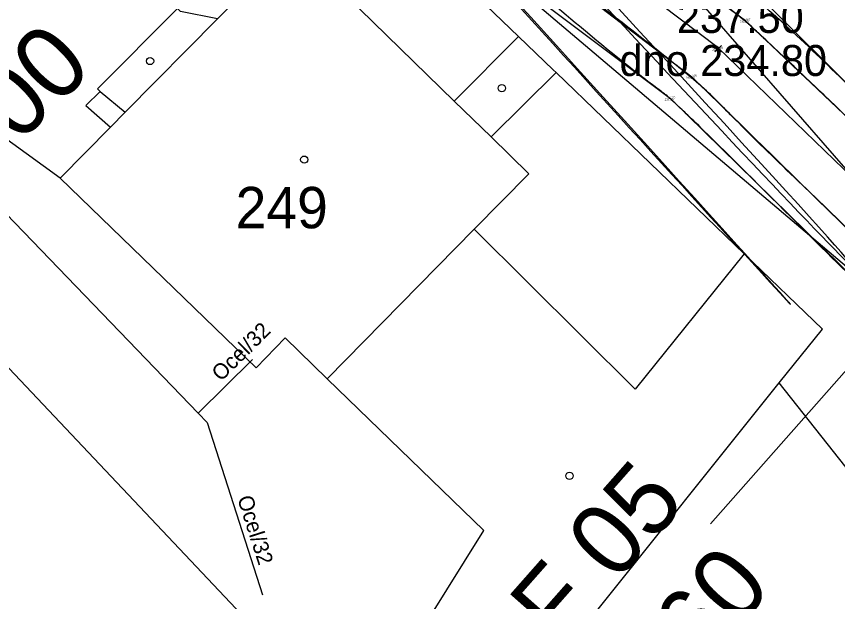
# Model space of a CAD drawing. Extents: x -555757 to -553364, y -1100723 to -1096439.
# Drawn here: x -554318.17 to -554278.45, y -1100564.79 to -1100536.48 of the extents above; entities that cross this region are included whole.
import ezdxf

# ---------------------------------------------------------------- set-up
doc = ezdxf.new("R2010")
doc.units = 0
for name, color, linetype in [('00_NÁVRH - 0.18 mm', 7, 'Continuous'), ('00_NÁVRH - 0.35 mm', 7, 'Continuous'), ('00_NÁVRH - Řezy', 7, 'Continuous'), ('01_HLADINA', 7, 'Continuous'), ('05_SÍTĚ - plynovod NTL', 7, 'Continuous'), ('05_SÍTĚ - vedení VN - nadzemní', 7, 'Continuous'), ('20', 7, 'Continuous'), ('BUDOVY', 7, 'Continuous'), ('C$SLO$PARCELY', 7, 'Continuous'), ('Geodet. výšky - netisknuté', 7, 'Continuous'), ('HRANA$SVAHU', 7, 'Continuous'), ('HRANICE$PARCELY', 7, 'Continuous'), ('OSA$KOLEJI', 7, 'Continuous'), ('POPIS', 7, 'Continuous'), ('ROZHRANI', 7, 'Continuous'), ('SLOUPY', 7, 'Continuous'), ('SLUCKOV$$C$RA', 7, 'Continuous'), ('VYSKA_PODR_BOD', 7, 'Continuous')]:
    doc.layers.add(name, color=color, linetype=linetype)

# ---------------------------------------------------------------- blocks, each defined once
blk = doc.blocks.new('POINT_DISPLAY')
blk.add_line((0, 0), (0, 0))
blk = doc.blocks.new('4$02')
at = {"layer": 'SLOUPY'}
blk.add_circle((0, 0), 0.175, dxfattribs=at)
blk = doc.blocks.new('BOD')
at = {"layer": 'POPIS'}
for p, q in [((-0.283, -0.283), (0.283, 0.283)), ((-0.283, 0.283), (0.283, -0.283))]:
    blk.add_line(p, q, dxfattribs=at)

msp = doc.modelspace()

# ---------------------------------------------------------------- linework, layer by layer
at = {"layer": '00_NÁVRH - 0.18 mm'}
msp.add_lwpolyline([(-554230.466, -1100601.206), (-554249.164, -1100583.038), (-554263.07, -1100566.98), (-554269.426, -1100554.136), (-554270.586, -1100551.573), (-554271.594, -1100550.189), (-554284.219, -1100538.005), (-554306.94, -1100520.848), (-554308.081, -1100519.365), (-554313.597, -1100512.423), (-554314.94, -1100505.715), (-554315.308, -1100495.76), (-554315.472, -1100482.811), (-554315.568, -1100470.17)], dxfattribs=at)
for points in [[(-554058.34, -1100594.24), (-554064.27, -1100591.415), (-554069.894, -1100588.736), (-554070.2, -1100588.59), (-554070.622, -1100588.302), (-554073.49, -1100586.347), (-554075.45, -1100585.01), (-554079.1, -1100582.531), (-554080.049, -1100581.874), (-554080.7, -1100581.481), (-554081.481, -1100581.304), (-554087.875, -1100580.272), (-554092.015, -1100579.605), (-554097.661, -1100578.708), (-554101.142, -1100578.133), (-554103.33, -1100577.967), (-554104.353, -1100578.095), (-554110.104, -1100579.897), (-554119.235, -1100582.7), (-554134.394, -1100587.389), (-554135.14, -1100587.62), (-554135.88, -1100587.767), (-554163.968, -1100593.356), (-554164.64, -1100593.5), (-554165.523, -1100593.676), (-554179.48, -1100596.685), (-554194.32, -1100599.87), (-554206.989, -1100602.104), (-554211.391, -1100602.887), (-554215.452, -1100603.598), (-554218.301, -1100604.127), (-554220.59, -1100604.491), (-554221.645, -1100604.411), (-554222.588, -1100604.119), (-554224.36, -1100602.886), (-554226.55, -1100601.265), (-554230.862, -1100598.151), (-554231.32, -1100597.82), (-554232.374, -1100596.759), (-554235.586, -1100593.426), (-554239.515, -1100589.37), (-554243.986, -1100584.748), (-554247.71, -1100580.92), (-554249.936, -1100577.477), (-554252.665, -1100573.15), (-554257.62, -1100565.38), (-554264.631, -1100555.299), (-554268.645, -1100549.529), (-554269.73, -1100547.97), (-554270.489, -1100547.211), (-554275.85, -1100541.875), (-554281.97, -1100535.78), (-554287.906, -1100531.237), (-554302.937, -1100521.677), (-554058.34, -1100594.24), (-554302.937, -1100521.677)], [(-554047.86, -1100606.09), (-554063.146, -1100601.815), (-554071.814, -1100599.393), (-554074.245, -1100598.71), (-554074.95, -1100598.43), (-554075.799, -1100598.044), (-554076.704, -1100597.516), (-554082.278, -1100594.33), (-554084.54, -1100593.047), (-554085.407, -1100592.634), (-554086.399, -1100592.326), (-554087.509, -1100592.104), (-554096.333, -1100590.269), (-554099.874, -1100589.549), (-554100.557, -1100589.404), (-554101.037, -1100589.369), (-554101.552, -1100589.414), (-554102.59, -1100589.645), (-554107.727, -1100590.768), (-554129.464, -1100595.608), (-554132.384, -1100596.23), (-554132.88, -1100596.318), (-554134.554, -1100596.539), (-554152.022, -1100598.865), (-554161.802, -1100600.155), (-554162.744, -1100600.318), (-554163.338, -1100600.456), (-554165.331, -1100601.02), (-554176.765, -1100604.247), (-554189.626, -1100607.8), (-554194.598, -1100609.179), (-554196.355, -1100609.599), (-554198.704, -1100609.736), (-554203.748, -1100609.834), (-554214.875, -1100610.027), (-554219.792, -1100610.102), (-554223.403, -1100610.173), (-554224.348, -1100610.104), (-554224.869, -1100609.756), (-554225.457, -1100609.217), (-554228.695, -1100606.291), (-554234.196, -1100601.385), (-554241.685, -1100594.776), (-554249.868, -1100587.59), (-554251.102, -1100586.477), (-554253.665, -1100583.954), (-554260.074, -1100577.697), (-554266.777, -1100571.14), (-554267.547, -1100570.379), (-554267.995, -1100569.734), (-554268.443, -1100568.902), (-554268.664, -1100568.278), (-554270.099, -1100564.014), (-554272.97, -1100555.371), (-554273.54, -1100553.674), (-554273.85, -1100553.041), (-554274.307, -1100552.435), (-554274.896, -1100551.869), (-554275.985, -1100550.799), (-554278.698, -1100548.209), (-554284.66, -1100542.226), (-554286.16, -1100540.826), (-554286.536, -1100540.462), (-554286.752, -1100540.28), (-554286.997, -1100540.101), (-554289.311, -1100538.365), (-554299.045, -1100530.122), (-554303.449, -1100525.797), (-554305.461, -1100524.163), (-554047.86, -1100606.09), (-554305.461, -1100524.163)]]:
    msp.add_open_spline(points, degree=3, dxfattribs=at)
at = {"layer": '00_NÁVRH - 0.35 mm'}
for points in [[(-554261.18, -1100566.187), (-554261.287, -1100566.026), (-554262.205, -1100564.307), (-554264.13, -1100560.566), (-554266.956, -1100555.04), (-554269.115, -1100550.897), (-554269.784, -1100549.561), (-554270.23, -1100548.864), (-554270.932, -1100548.082), (-554271.706, -1100547.35), (-554272.831, -1100546.276), (-554274.362, -1100544.823), (-554276.402, -1100542.876), (-554279.345, -1100540.052), (-554281.593, -1100537.929), (-554282.318, -1100537.246), (-554282.905, -1100536.713), (-554283.251, -1100536.425), (-554284.229, -1100535.698), (-554285.73, -1100534.585), (-554286.937, -1100533.66), (-554288.679, -1100532.362), (-554296.351, -1100526.833), (-554303.325, -1100522.059), (-554261.234, -1100566.107), (-554299.826, -1100524.428)], [(-554264.589, -1100568.17), (-554264.717, -1100567.968), (-554265.365, -1100566.881), (-554266.161, -1100565.265), (-554268.948, -1100559.629), (-554270.726, -1100555.972), (-554272.297, -1100552.9), (-554272.836, -1100551.874), (-554273.561, -1100551.08), (-554275.318, -1100549.374), (-554278.961, -1100545.794), (-554283.166, -1100541.692), (-554284.82, -1100540.047), (-554285.492, -1100539.455), (-554286.639, -1100538.528), (-554295.981, -1100531.243), (-554303.386, -1100525.154), (-554305.07, -1100523.778), (-554264.653, -1100568.069), (-554304.227, -1100524.466)]]:
    msp.add_open_spline(points, degree=3, dxfattribs=at)
at = {"layer": '00_NÁVRH - Řezy'}
msp.add_line((-554284.593, -1100561.029), (-554264.872, -1100538.673), dxfattribs=at)
at = {"layer": '01_HLADINA'}
for points in [[(-554303.325, -1100522.059), (-554300.992, -1100523.638), (-554296.049, -1100526.985), (-554290.632, -1100530.919), (-554287.105, -1100533.522), (-554285.641, -1100534.66), (-554284.408, -1100535.575), (-554283.446, -1100536.259), (-554282.815, -1100536.784), (-554282.268, -1100537.291), (-554281.086, -1100538.41), (-554279.101, -1100540.272), (-554276.707, -1100542.588), (-554274.536, -1100544.663), (-554272.962, -1100546.145), (-554271.829, -1100547.242), (-554270.928, -1100548.07), (-554270.249, -1100548.784), (-554269.657, -1100549.746), (-554268.678, -1100551.862), (-554266.678, -1100555.472), (-554264.463, -1100559.99), (-554262.518, -1100563.617), (-554261.613, -1100565.54), (-554261.216, -1100566.134), (-554261.18, -1100566.187)], [(-554265.965, -1100565.681), (-554266.03, -1100565.542), (-554266.988, -1100563.505), (-554268.662, -1100560.317), (-554270.589, -1100556.128), (-554272, -1100553.616), (-554272.759, -1100551.855), (-554273.895, -1100550.757), (-554275.953, -1100548.764), (-554279.126, -1100545.594), (-554282.36, -1100542.557), (-554284.454, -1100540.357), (-554285.634, -1100539.323), (-554289.349, -1100536.38), (-554295.457, -1100531.794), (-554301.469, -1100526.714), (-554304.508, -1100524.236), (-554305.07, -1100523.778)]]:
    msp.add_open_spline(points, degree=3, dxfattribs=at)
at = {"layer": '05_SÍTĚ - plynovod NTL'}
for p, q in [((-554309.389, -1100555.68), (-554332.471, -1100531.718)), ((-554306.756, -1100553.082), (-554309.389, -1100555.68))]:
    msp.add_line(p, q, dxfattribs=at)
msp.add_lwpolyline([(-554309.389, -1100555.68), (-554308.953, -1100556.122), (-554306.277, -1100564.461)], dxfattribs=at)
at = {"layer": '05_SÍTĚ - vedení VN - nadzemní'}
msp.add_lwpolyline([(-554324.546, -1100507.473), (-554320.113, -1100512.256), (-554293.478, -1100535.466), (-554257.717, -1100565.776), (-554219.756, -1100599.256), (-554187.611, -1100626.856)], dxfattribs=at)
at = {"layer": 'HRANA$SVAHU'}
for p, q in [((-554282.9, -1100536.69), (-554305.87, -1100519.48)), ((-554308.19, -1100522.08), (-554285.5, -1100539.4)), ((-554308.62, -1100523.87), (-554286.53, -1100540.45)), ((-554269.73, -1100547.97), (-554281.97, -1100535.78)), ((-554270.18, -1100548.8), (-554282.9, -1100536.69)), ((-554285.5, -1100539.4), (-554272.8, -1100551.83)), ((-554286.53, -1100540.45), (-554273.78, -1100552.96))]:
    msp.add_line(p, q, dxfattribs=at)
at = {"layer": 'HRANICE$PARCELY'}
for p, q in [((-554293.88, -1100537.46), (-554310.88, -1100521.06)), ((-554333.45, -1100537.74), (-554301.75, -1100571.27)), ((-554290.74, -1100566.04), (-554281.28, -1100554.21))]:
    msp.add_line(p, q, dxfattribs=at)
for points in [[(-554304.43, -1100516.2), (-554284.85, -1100536.07), (-554272.37, -1100550.38)], [(-554293.88, -1100537.46), (-554296.99, -1100540.58), (-554304.83, -1100532.92), (-554308.45, -1100536.59), (-554310.24, -1100536.24), (-554310.38, -1100536.1), (-554314.25, -1100539.99), (-554314.13, -1100540.12), (-554314.82, -1100540.79), (-554313.62, -1100541.84), (-554316.06, -1100544.31), (-554329.35, -1100534.66)], [(-554281.28, -1100554.21), (-554279.17, -1100551.62), (-554282.97, -1100547.96), (-554292.07, -1100539.2), (-554292.2, -1100539.07), (-554293.88, -1100537.46)], [(-554243.2, -1100602.05), (-554267.54, -1100571.55), (-554268.43, -1100570.43), (-554281.28, -1100554.21)]]:
    msp.add_lwpolyline(points, dxfattribs=at)
at = {"layer": 'SLUCKOV$$C$RA'}
for p, q in [((-554312.92, -1100541.12), (-554308.45, -1100536.59)), ((-554295.21, -1100542.31), (-554292.07, -1100539.2)), ((-554314.13, -1100540.12), (-554312.92, -1100541.12)), ((-554296.99, -1100540.58), (-554295.21, -1100542.31)), ((-554313.62, -1100541.84), (-554312.92, -1100541.12)), ((-554293.38, -1100544.1), (-554295.21, -1100542.31)), ((-554296.03, -1100546.78), (-554293.38, -1100544.1)), ((-554316.06, -1100544.31), (-554306.58, -1100553.49)), ((-554303.14, -1100554.01), (-554296.03, -1100546.78)), ((-554288.24, -1100554.52), (-554296.03, -1100546.78)), ((-554282.97, -1100547.96), (-554288.24, -1100554.52)), ((-554306.58, -1100553.49), (-554305.17, -1100552.03)), ((-554305.17, -1100552.03), (-554303.14, -1100554.01)), ((-554303.14, -1100554.01), (-554295.56, -1100561.36)), ((-554301.75, -1100571.27), (-554295.56, -1100561.36))]:
    msp.add_line(p, q, dxfattribs=at)

# ---------------------------------------------------------------- block references
at = {"layer": 'BUDOVY'}
for p in [(-554311.71, -1100538.64), (-554294.69, -1100539.95), (-554304.25, -1100543.41), (-554291.42, -1100558.71)]:
    msp.add_blockref('4$02', p, dxfattribs=at)
at = {"layer": 'POPIS', "xscale": 0.5624965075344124, "yscale": 0.5624965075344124}
msp.add_blockref('BOD', (-554284.23, -1100538.04), dxfattribs=at)
at = {"layer": 'ROZHRANI'}
for p in [(-554282.9, -1100536.69), (-554284.23, -1100538.04), (-554285.5, -1100539.4), (-554286.53, -1100540.45)]:
    msp.add_blockref('POINT_DISPLAY', p, dxfattribs=at)

# ---------------------------------------------------------------- texts
at = {"layer": '00_NÁVRH - Řezy'}
for s, rotation, p in [('km 0,300', 44.5788, (-554328.096, -1100552.552)), ('PF 05', 48.5833, (-554293.98, -1100569.382)), ('km 0,260', 48.5833, (-554294.276, -1100578.555))]:
    msp.add_text(s, height=3.5, rotation=rotation, dxfattribs=at).set_placement(p)
at = {"layer": '20'}
for rotation, p in [(44.6166, (-554308.281, -1100554.172)), (287.794, (-554307.498, -1100559.792))]:
    msp.add_text('Ocel/32', height=0.75, rotation=rotation, dxfattribs=at).set_placement(p)
at = {"layer": 'C$SLO$PARCELY'}
msp.add_text('249', height=2, dxfattribs=at).set_placement((-554307.571, -1100546.73))
at = {"layer": 'Geodet. výšky - netisknuté'}
for s, p in [('234.90', (-554283.183, -1100536.79)), ('234.80', (-554284.513, -1100538.14)), ('235.00', (-554285.783, -1100539.5)), ('237.50', (-554286.813, -1100540.55))]:
    msp.add_text(s, height=0.1, dxfattribs=at).set_placement(p)
at = {"layer": 'OSA$KOLEJI'}
for s, p in [('167', (-554282.9, -1100536.69)), ('168', (-554284.23, -1100538.04)), ('169', (-554285.5, -1100539.4)), ('170', (-554286.53, -1100540.45))]:
    msp.add_text(s, height=0.1, dxfattribs=at).set_placement(p)
at = {"layer": 'POPIS'}
msp.add_text('dno 234.80', height=1.5, dxfattribs=at).set_placement((-554288.998, -1100539.363))
at = {"layer": 'VYSKA_PODR_BOD'}
msp.add_text('237.50', height=1.5, dxfattribs=at).set_placement((-554286.22, -1100537.28))

doc.saveas('drawing.dxf')
